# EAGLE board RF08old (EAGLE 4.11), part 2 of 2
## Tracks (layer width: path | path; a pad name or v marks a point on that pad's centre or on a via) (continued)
DMA09  (via drill 0.61) (continued)
  Bottom 0.254: v114.3,77.48 81.92,77.48 v81.28,76.85 | v79.38,72.41 v59.05,72.41 | v59.05,47.01 45.09,47.01 43.81,48.27 RS08.19 40.64,48.27 39.37,49.55 35.56,49.55 v34.29,50.81 | v115.57,81.3 DMA8-11.6 | v149.22,87.01 150.5,87.01 151.13,86.38 IC24.6 | v135.89,101.61 v148.59,101.61 | v138.43,128.28 137.79,128.92 v114.94,128.92
DMA10  (via drill 0.61)
  Top 0.254: v40.64,45.73 41.27,46.37 41.27,50.81 40.01,52.09 41.27,53.36 v41.27,58.44 | v50.8,43.2 v50.8,48.91 | v81.28,57.16 82.55,58.44 v82.55,61.61 | v101.6,62.88 104.14,65.42 104.14,81.3 101.6,83.83 v101.6,91.45
  Bottom 0.254: v41.27,58.44 40.01,59.7 34.92,59.7 33.66,58.44 SV2.21 | v40.64,45.73 RS08.21 43.18,45.1 44.45,43.83 44.45,42.56 45.09,41.92 48.9,41.92 50.16,43.2 v50.8,43.2 | IC24.4 151.13,91.45 149.86,90.19 128.27,90.19 127.64,90.82 123.83,90.82 123.19,91.45 DMA8-11.2 v101.6,91.45 | v50.8,48.91 51.44,49.55 57.15,49.55 59.69,52.09 62.23,52.09 67.31,57.16 v81.28,57.16 | v82.55,61.61 83.82,62.88 v101.6,62.88
DMA11  (via drill 0.61)
  Top 0.254: v31.75,48.27 31.75,53.99 33.02,55.26 SV2.23 | v39.37,48.27 38.73,47.64 38.73,46.37 38.1,45.73 38.1,17.8 v39.37,16.53 | v65.41,19.7 67.31,21.61 67.31,31.77 v69.85,34.3 | v96.52,35.58 103.5,42.56 103.5,63.52 104.78,64.78 104.78,81.93 v104.14,82.56 | v110.49,83.83 114.3,87.64 v114.3,88.28
  Bottom 0.254: RS08.23 27.3,43.2 26.67,42.56 25.4,43.83 25.4,48.27 v31.75,48.27 34.29,45.73 36.83,48.27 v39.37,48.27 | IC24.2 155.57,96.53 156.84,97.81 161.93,97.81 161.93,90.82 161.29,90.19 151.13,90.19 148.59,87.64 124.46,87.64 123.19,88.92 DMA8-11.3 114.94,88.92 v114.3,88.28 | v39.37,16.53 40.01,15.89 61.59,15.89 v65.41,19.7 | v69.85,34.3 76.83,34.3 78.11,35.58 v96.52,35.58 | v104.14,82.56 105.41,83.83 v110.49,83.83
DMA-IN\  (via drill 0.61)
  Top 0.254: v26.67,13.99 22.23,18.43 22.23,33.04 20.32,34.94 20.32,38.12 IC34.1 17.78,48.27 19.68,50.18 19.68,71.77 IC26.1 17.78,76.85 19.05,78.12 19.05,109.23 20.32,110.5 IC13.4
  Bottom 0.254: v26.67,13.99 36.2,13.99 39.37,10.81 71.75,10.81 IC41.12 | IC26.19 21.59,71.14 19.05,73.67 IC26.1
DMA-OUT\  (via drill 0.61)
  Top 0.254: IC28.19 62.87,69.23 62.87,40.02 IC35.19 | v64.77,21.61 v64.77,38.12 | v80.64,18.43 IC41.9 | IC28.1 51.44,71.77 51.44,49.55 52.7,48.27 52.7,41.29 IC35.1
  Bottom 0.254: IC35.1 54.61,40.66 57.15,38.12 IC35.19 v64.77,38.12 | v80.64,18.43 80.01,17.8 68.58,17.8 v64.77,21.61
DONE  (via drill 0.61)
  Top 0.254: v135.25,25.41 135.25,22.24 IC55.2 | v179.07,24.14 181.61,26.69 181.61,61.61 182.25,62.24 182.25,83.2 186.69,87.64 186.69,90.82 184.15,93.36 184.15,113.05 186.69,115.58 | 186.69,115.58 187.96,116.86 IC11.9 | v22.86,36.84 22.86,41.29 22.23,41.92 v22.23,63.52 | v13.97,64.78 14.61,65.42 14.61,90.82 13.97,91.45 13.97,115.58 16.51,118.12 16.51,125.75 20.95,130.19 24.13,130.19 24.13,133.36 21.59,135.9 v21.59,140.35 | v172.09,147.97 186.69,133.36 186.69,115.58
  Bottom 0.254: v135.25,25.41 136.53,26.69 140.34,26.69 142.88,24.14 v179.07,24.14 | v22.86,36.84 33.66,36.84 34.92,38.12 SV1.23 | v22.23,63.52 20.95,64.78 v13.97,64.78 | v21.59,140.35 19.05,142.89 19.05,148.6 55.88,148.6 56.52,149.24 98.42,149.24 99.69,147.97 102.23,147.97 102.87,148.6 120.02,148.6 120.65,147.97 v172.09,147.97
DRV01\  (via drill 0.61)
  Top 0.254: v69.85,12.71 73.66,8.91 IC41.4 | v55.88,12.71 51.44,17.16 v51.44,24.14
  Bottom 0.254: v55.88,12.71 v69.85,12.71 | v51.44,24.14 50.16,25.41 RS08.38
DRV23\  (via drill 0.61)
  Top 0.254: v78.74,44.47 78.11,43.83 78.11,19.7 80.01,17.8 80.01,10.18 81.28,8.91 IC41.7
  Bottom 0.254: v78.74,44.47 47.62,44.47 46.35,45.73 RS08.22
DRVOK\  (via drill 0.61)
  Top 0.254: R2.1 RS08.40 | v46.99,93.36 46.99,97.81 46.35,98.44 46.35,102.25 45.72,102.89 IC21.14 | v53.34,78.75 v53.34,93.36 | v58.42,78.75 57.78,78.12 57.78,43.2 59.05,41.92 59.05,34.94 58.42,34.3 58.42,32.4 57.78,31.77 v57.78,21.61
  Bottom 0.254: IC21.14 46.35,103.52 47.62,103.52 IC21.13 | v53.34,93.36 v46.99,93.36 | v58.42,78.75 v53.34,78.75 | v57.78,21.61 47.62,21.61 46.35,22.88 RS08.40
EIE  (via drill 0.61)
  Top 0.254: IC37.2 194.31,24.14 194.31,8.91 193.68,8.27 187.96,8.27 INTENB.6 | v38.1,3.19 38.1,9.54 35.56,12.08 SV1.3 | v99.69,3.19 102.87,6.36 102.87,19.7 104.14,20.97 v104.14,22.88 | v139.7,24.14 142.88,20.97 142.88,12.08 IC55.9
  Bottom 0.254: IC55.9 146.05,10.18 147.32,8.91 170.18,8.91 171.45,7.63 185.42,7.63 INTENB.6 | v38.1,3.19 v99.69,3.19 | v104.14,22.88 105.41,24.14 v139.7,24.14
ERROR  (via drill 0.61)
  Top 0.254: v147.32,100.34 147.32,36.84 148.59,35.58 148.59,16.53 IC55.10 | v194.31,123.2 194.31,116.22 196.22,114.31 196.22,100.98 IC12.6
  Bottom 0.254: v147.32,100.34 195.58,100.34 196.85,99.08 IC12.6 | v194.31,123.2 191.13,126.38 177.16,126.38 IC7.2
EXAD0\  (via drill 0.61)
  Top 0.254: v4.45,77.48 5.08,76.85 5.08,66.69 7.62,64.15 C35L.34
  Bottom 0.254: v4.45,77.48 19.68,92.72 24.13,92.72 IC20.9
EXAD1\  (via drill 0.61)
  Top 0.254: v8.26,92.72 5.71,90.19 5.71,67.33 6.99,66.06 C35L.36
  Bottom 0.254: v8.26,92.72 8.89,92.72 9.53,93.36 19.68,93.36 IC20.7
EXAD2\  (via drill 0.61)
  Top 0.254: v8.89,94 9.53,93.36 9.53,72.41 8.89,71.77 8.89,70.5 7.62,69.23 C35L.38
  Bottom 0.254: v8.89,94 15.24,94 IC20.5
F.1  (via drill 0.61)
  Top 0.254: SV2.6 35.56,80.03 32.38,80.03 31.75,80.66 31.75,84.47 32.38,85.11 32.38,86.38 31.75,87.01 31.75,101.61 30.48,102.89 IC20.11 30.48,105.42 31.11,106.06 v31.11,111.78 | v194.94,45.73 194.31,46.37 v194.31,81.3 194.31,101.61 v193.68,102.25 | v170.18,111.78 172.09,109.87 v172.09,103.52
  Bottom 0.254: v194.94,45.73 195.58,45.73 IC30.8 | v194.31,81.3 196.85,83.83 FIELD.3 | v31.11,111.78 38.73,111.78 39.37,112.41 39.37,113.68 64.77,113.68 65.41,114.31 88.27,114.31 90.81,111.78 92.08,111.78 92.71,112.41 92.71,113.68 116.84,113.68 120.65,109.87 165.74,109.87 167.64,111.78 v170.18,111.78 | v172.09,103.52 173.35,102.25 v193.68,102.25
F.2  (via drill 0.61)
  Top 0.254: v24.13,83.2 24.13,101.61 25.4,102.89 IC20.13 | v57.78,81.93 57.78,82.56 56.52,83.83 55.24,83.83 55.24,77.48 55.88,76.85 55.88,75.58 55.24,74.95 52.07,74.95 v52.07,78.75 | v85.09,79.39 86.36,78.12 v86.36,76.22 | v113.03,72.41 v111.12,74.31 | v127.64,71.14 127,70.5 v127,63.52 | v196.85,64.78 201.29,69.23 v201.29,78.12
  Bottom 0.254: v24.13,83.2 27.3,80.03 33.66,80.03 34.92,81.3 SV2.4 36.2,81.3 36.83,81.93 55.88,81.93 56.52,81.3 57.15,81.3 v57.78,81.93 | 210.19,77.48 210.19,87.64 200.66,87.64 199.39,86.38 FIELD.2 | 210.19,77.48 210.19,42.56 IC30.11 | v52.07,78.75 53.34,80.03 78.11,80.03 78.74,79.39 80.01,79.39 80.64,78.75 84.45,78.75 v85.09,79.39 | v86.36,76.22 87,75.58 102.23,75.58 103.5,74.31 v111.12,74.31 | v113.03,72.41 124.46,72.41 125.73,71.14 v127.64,71.14 | v127,63.52 168.28,63.52 169.54,64.78 v196.85,64.78 | v201.29,78.12 201.93,77.48 210.19,77.48
F.3  (via drill 0.61)
  Top 0.254: SV2.2 35.56,97.17 v33.66,99.08 v33.66,125.11 | v90.81,121.3 v88.9,123.2 | v158.75,121.94 161.29,121.94 161.29,125.75 v162.56,127.02 | v193.68,127.02 194.31,127.65 194.31,131.46 198.75,135.9 201.29,135.9 201.29,79.39 FIELD.6
  Bottom 0.254: v33.66,99.08 25.4,99.08 IC20.15 | FIELD.6 199.39,76.22 200.66,74.95 207.01,74.95 209.55,72.41 209.55,43.83 206.38,43.83 IC30.13 | v33.66,125.11 34.92,126.38 59.05,126.38 62.87,122.57 88.27,122.57 v88.9,123.2 | v90.81,121.3 91.44,121.94 v158.75,121.94 | v193.68,127.02 v162.56,127.02
GND  (via drill 0.61)
  Top 0.254: IC34.10 17.14,17.16 17.14,16.53 15.88,15.26 10.16,15.26 C35L.1 C35L.3 C35L.5 C35L.7 C35L.9 C35L.11 C35L.13 C35L.15 C35L.17 C35L.19 C35L.21 C35L.23 C35L.25 C35L.27 C35L.29 C35L.31 C35L.33 C35L.35 C35L.37 C35L.39 | C35.2 54.61,43.83 53.98,44.47 53.98,50.18 IC28.10 | SV2.26 v35.56,50.81 | IC21.8 58.42,95.27 54.61,91.45 C28.2 | 92.71,112.41 93.34,111.78 IC16.1 93.98,115.58 96.52,118.12 IC16.15 | 92.71,112.41 92.08,113.05 C16.2 | 92.71,112.41 92.71,99.71 91.44,98.44 C33.2 | IC13.2 IC20.17 | IC14.2 IC14.13 | C42.2 138.43,62.88 137.79,63.52 137.79,73.04 137.16,73.67 DAR8-11.8 135.25,78.12 135.25,84.47 DAR8-11.4 139.06,88.28 139.06,96.53 C27.2 138.43,97.17 140.34,99.08 140.34,111.14 IC17.8 | C24.2 153.03,101.61 149.22,105.42 146.69,105.42 146.69,113.05 C18.2 | IC31.10 153.67,40.66 C38.2 | DAR4-7.4 135.25,50.18 135.25,43.83 DAR4-7.8 137.16,27.32 138.43,26.05 C40.2 | C8.2 123.83,96.53 123.83,88.28 DMA8-11.4 120.02,84.47 120.02,78.12 DMA8-11.8 122.56,75.58 122.56,62.24 C39.2 | DMA0-3.4 120.02,19.7 120.02,26.05 121.92,27.96 C46.2 | D36L.1 D36L.3 D36L.5 D36L.7 D36L.9 D36L.11 D36L.13 D36L.15 D36L.17 D36L.19 D36L.21 D36L.23 D36L.25 D36L.27 D36L.29 D36L.31 D36L.33 D36L.35 D36L.37 D36L.39 | D35L.1 D35L.3 D35L.5 D35L.7 D35L.9 D35L.11 D35L.13 D35L.15 D35L.17 D35L.19 D35L.21 D35L.23 D35L.25 D35L.27 D35L.29 D35L.31 D35L.33 D35L.35 D35L.37 D35L.39 | RS08.39 43.18,23.51 44.45,24.78 44.45,31.13 43.18,32.4 RS08.31 | 62.87,26.05 62.87,24.78 IC35.13 62.87,20.97 62.87,16.53 59.05,12.71 | IC35.15 62.87,26.05 | 62.87,26.05 62.87,31.13 IC35.17 | 59.05,12.71 54.61,17.16 54.61,17.8 IC35.10
  Top 0.254: 59.05,12.71 62.87,8.91 C41.2 | J14.2 J13.2 J12.2 J11.2 J10.2 J9.2 J8.2 | IC24.10 153.67,74.95 C31.2 | D34L.39 D34L.37 D34L.35 D34L.33 D34L.31 D34L.29 D34L.27 D34L.25 D34L.23 D34L.21 D34L.19 D34L.17 D34L.15 D34L.13 D34L.11 D34L.9 D34L.7 D34L.5 D34L.3 D34L.1 172.72,22.24 173.99,20.97 173.99,13.35 172.72,12.08 C43.2 | 161.93,14.62 161.93,15.89 | 161.93,15.89 IC38.15 | IC38.13 161.93,14.62 | 161.93,15.89 161.93,20.97 IC38.17 | 161.93,14.62 161.93,9.54 IC38.11 | v185.42,99.08 186.69,97.81 186.69,92.09 187.96,90.82 IC19.7 | C36L.39 C36L.37 C36L.35 C36L.33 C36L.31 C36L.29 C36L.27 C36L.25 C36L.23 C36L.21 C36L.19 C36L.17 C36L.15 C36L.13 C36L.11 C36L.9 C36L.7 C36L.5 C36L.3 C36L.1 190.5,21.61 193.04,19.07 INTENB.9 189.23,13.99 | 189.23,13.99 INTENB.5 | 189.23,13.99 INTENB.8 | C37.2 199.39,33.67 197.49,35.58 197.49,37.48 IC30.10 | FIELD.8 196.22,73.04 196.22,76.85 FIELD.5 197.49,79.39 197.49,80.66 FIELD.4 200.03,83.2 200.03,91.45 C44.2 199.39,95.27 IC12.7 200.03,98.44 200.03,114.31 C12.2 199.39,114.95 200.66,116.22 200.66,129.55 IC8.1 199.39,133.36 C47.2 | IC7.8 190.5,123.2 191.77,121.94 191.77,114.31 190.5,113.05 IC11.7 | 173.35,135.27 175.26,133.36 IC7.15 | 173.35,135.27 173.35,138.44 C45.- | C11.2 172.72,113.68 170.18,116.22 C7.2 170.18,126.38 171.45,127.65 171.45,133.36 173.35,135.27 | IC9.12 124.46,130.82 123.19,129.55 123.19,127.02 121.92,125.75 IC9.2 | C17.2 119.38,113.68 116.84,116.22 C9.2 116.84,126.38 118.11,127.65 118.11,136.54 116.84,137.81 C5.2 | IC10.12 152.4,130.82 151.13,129.55 151.13,127.65 149.86,126.38 IC10.2 | C6.2 144.78,137.81 144.15,137.17 144.15,132.09 143.51,131.46 143.51,127.65 144.78,126.38 C10.2
  Top 0.254: IC4.7 107.31,136.54 108.58,136.54 IC4.8 | IC3.7 79.38,136.54 80.64,136.54 IC3.8 | IC2.7 51.44,136.54 52.7,136.54 IC2.8 | IC17.15 127.64,122.57 130.81,122.57 130.81,125.75 131.44,126.38 134.62,126.38 IC9.7
  Bottom 0.254: C35L.17 C34.2 | SV2.26 SV2.25 32.38,53.36 31.75,52.72 27.3,52.72 26.67,52.09 20.32,52.09 19.05,50.81 IC26.10 C35L.23 | J2.2 5.71,50.81 6.99,52.09 8.26,52.09 9.53,53.36 C35L.25 | v35.56,50.81 36.2,50.18 40.01,50.18 40.64,49.55 46.35,49.55 46.99,50.18 51.44,50.18 52.07,50.81 IC28.10 | C22.2 59.69,97.81 IC21.8 56.52,98.44 38.1,98.44 C21.2 30.48,97.81 IC20.10 | IC25.8 99.69,71.77 95.89,71.77 IC25.5 92.08,71.77 83.19,71.77 80.01,74.95 | 80.01,74.95 56.52,74.95 55.24,76.22 C28.2 | 80.01,74.95 C25.2 | IC22.7 85.09,97.81 C33.2 | IC16.8 109.86,109.87 95.89,109.87 IC16.1 93.34,111.14 84.45,111.14 IC15.7 81.92,113.68 74.3,113.68 | IC17.15 121.92,116.86 99.06,116.86 IC16.15 | IC20.10 30.48,95.27 26.04,90.82 24.77,90.82 19.68,85.74 19.05,85.74 C26.2 2.54,76.22 2.54,74.95 3.81,73.67 6.99,73.67 9.53,71.14 C35L.39 | C13.2 10.79,113.05 11.43,112.41 12.06,112.41 IC13.1 13.34,111.14 14.61,111.14 IC13.2 17.14,109.87 26.04,109.87 IC13.7 | 6.35,98.44 10.16,102.25 13.34,102.25 IC20.17 | 6.35,98.44 5.71,97.81 C20.2 | 74.3,113.68 66.04,113.68 C15.2 57.15,113.05 IC14.7 53.98,109.87 46.35,109.87 | 74.3,113.68 IC15.4 | IC13.7 29.21,113.05 C14.2 | 46.35,109.87 45.09,109.87 IC14.2 42.55,111.14 41.27,111.14 IC14.1 40.64,110.5 29.21,110.5 IC13.7 | 46.35,109.87 IC14.4 | 6.35,98.44 28.57,98.44 IC20.10 | IC17.8 140.34,112.41 146.05,112.41 146.69,113.05 C18.2 147.96,113.05 148.59,113.68 172.72,113.68 | IC31.10 151.13,41.92 149.86,40.66 139.7,40.66 138.43,41.92 DAR4-7.8 135.89,41.92 134.62,40.66 125.09,40.66 123.83,41.92 DMA4-7.8 120.65,41.92 119.38,43.2 D36L.17 | D36L.5 C46.2 | DMA4-7.4 120.65,52.09 119.38,53.36 D36L.25
  Bottom 0.254: C39.2 122.56,62.24 121.28,63.52 D36L.33 | C27.2 137.79,96.53 136.53,97.81 126.36,97.81 125.09,96.53 C8.2 | 80.01,23.51 79.38,22.88 D35L.1 | 80.01,23.51 80.64,24.14 C36.2 | 80.01,23.51 82.55,20.97 89.53,20.97 IC36.4 92.08,22.24 93.34,22.24 IC36.5 95.89,20.97 99.69,20.97 IC36.8 102.23,22.24 102.87,22.24 103.5,21.61 112.39,21.61 113.67,22.88 D36L.1 | D35L.31 79.38,60.98 80.64,59.7 C29.2 81.28,60.34 92.08,60.34 IC29.5 95.89,56.53 99.69,56.53 IC29.8 | D35L.19 79.38,45.73 80.64,44.47 C32.2 81.28,45.1 92.08,45.1 | 92.08,45.1 IC32.5 | 92.08,45.1 99.69,45.1 IC32.8 | DMA0-3.8 IC23.7 107.31,5.73 98.42,5.73 IC23.2 94.61,9.54 91.44,9.54 C23.2 85.09,8.91 IC41.8 81.92,9.54 63.5,9.54 C41.2 | RS08.31 43.81,33.04 45.09,34.3 54.61,34.3 55.88,33.04 IC35.17 | D35L.5 73.03,27.96 71.75,26.69 66.67,26.69 65.41,27.96 IC35.15 | D34L.17 J6.2 | C31.2 154.31,67.33 155.57,68.59 168.28,68.59 169.54,67.33 170.81,67.33 172.09,68.59 D34L.37 | D34L.13 J8.2 | IC55.7 138.43,7.63 139.7,6.36 149.86,6.36 151.13,7.63 IC38.10 IC38.11 | IC38.13 161.29,12.71 161.93,12.08 172.72,12.08 C43.2 173.35,11.45 173.99,12.08 180.97,12.08 INTENB.4 183.51,9.54 184.78,9.54 INTENB.5 | IC19.7 190.5,91.45 C44.2 | v185.42,99.08 C19.2 | C36L.21 IC30.6 | FIELD.9 FIELD.8 C36L.39 | C36L.33 C30.2 | INTENB.8 195.58,7.63 IC37.10 | INTENB.9 IC37.6 | C36L.13 IC30.10 | C12.2 198.75,114.31 197.49,113.05 191.77,113.05 IC11.7 188.59,113.68 172.72,113.68 | IC6.8 167,139.08 171.45,139.08 C45.- | IC18.7 166.37,113.05 C11.2 172.72,113.68 | IC7.1 171.45,125.75 C7.2 163.83,125.75 IC10.7 160.66,126.38 147.96,126.38 | IC17.1 120.65,113.05 C17.2
  Bottom 0.254: C9.2 116.84,126.38 120.02,126.38 IC9.2 123.83,126.38 132.72,126.38 IC9.7 135.89,125.75 C10.2 144.78,126.38 147.96,126.38 | IC5.7 135.25,137.81 144.78,137.81 C6.2 | 147.96,126.38 IC10.2 | C5.2 116.2,138.44 115.57,137.81 109.86,137.81 IC4.8 | IC3.8 81.92,137.81 87.63,137.81 88.27,138.44 C4.2 88.9,139.08 104.78,139.08 IC4.7 | IC2.8 53.98,137.81 59.69,137.81 60.33,138.44 C3.2 60.96,139.08 76.83,139.08 IC3.7 | C1.2 5.71,138.44 6.35,139.08 20.95,139.08 IC1.7 23.5,136.54 24.77,136.54 IC1.8 26.04,137.81 31.75,137.81 32.38,138.44 C2.2 33.02,139.08 48.9,139.08 IC2.7
INT_RQ\  (via drill 0.61)
  Top 0.254: IC55.3 135.25,15.89 135.25,12.08 IC55.6 | v149.22,55.9 149.22,12.08 IC55.8
  Bottom 0.254: IC55.6 138.43,10.18 140.97,7.63 IC55.8 | v149.22,55.9 153.67,55.9 156.21,58.44 D34L.30
IOS\  (via drill 0.61)
  Top 0.254: v111.76,131.46 111.76,128.92 90.81,128.92 82.55,120.67 82.55,109.23 78.74,105.42 IC22.10 | v186.69,135.9 189.23,133.36 v189.23,99.08 | v169.54,92.09 168.91,91.45 168.91,57.8 170.18,56.53 D34L.28
  Bottom 0.254: v111.76,131.46 114.94,134.63 157.48,134.63 158.12,135.27 186.06,135.27 v186.69,135.9 | v189.23,99.08 189.23,92.09 v169.54,92.09
MYDEV\
  Top 0.254: 90.17,55.9 91.44,57.16 IC29.4 | 90.17,55.9 90.17,45.73 91.44,44.47 IC32.4 | 90.17,55.9 90.17,71.14 91.44,72.41 IC25.4
  Bottom 0.254: IC32.4 99.06,35.58 PAD1.1
N$1
  Top 0.254: IC36.9 PAD8.1
N$2  (via drill 0.61)
  Top 0.254: v179.07,129.55 181.61,127.02 181.61,121.94 182.88,120.67 IC11.11
  Bottom 0.254: v179.07,129.55 165.1,129.55 IC10.8
N$3  (via drill 0.61)
  Top 0.254: v125.73,49.55 126.36,48.91 126.36,40.66 125.09,39.38 125.09,31.77 125.73,31.13 125.73,30.5 125.09,29.86 125.09,18.43 DMA0-3.5
  Bottom 0.254: v125.73,49.55 DMA4-7.12
N$4  (via drill 0.61)
  Top 0.254: SW1.1 8.26,123.84 9.53,123.84 SW1.2 10.79,123.84 12.06,123.84 SW1.3 13.34,123.84 14.61,123.84 SW1.4 | 19.05,123.84 18.41,123.84 SW1.5 | 19.05,123.84 19.68,123.84 SW1.6 20.95,123.84 22.23,123.84 SW1.7 | v49.53,115.58 49.53,110.5 46.99,107.97 46.99,99.08 48.26,97.81 IC21.4 | v20.32,114.31 19.05,115.58 19.05,123.84
  Bottom 0.254: SW1.5 17.14,123.84 15.88,123.84 SW1.4 | SW1.8 24.77,123.84 23.5,123.84 SW1.7 | v49.53,115.58 26.67,115.58 25.4,114.31 v20.32,114.31
N$5
  Top 0.254: IC36.15 PAD2.1
N$6
  Top 0.254: IC36.14 PAD3.1
N$7
  Top 0.254: IC36.13 PAD4.1
N$8
  Top 0.254: IC36.12 PAD5.1
N$9
  Top 0.254: IC36.11 PAD6.1
N$10
  Top 0.254: IC36.10 PAD7.1
N$11  (via drill 0.61)
  Top 0.254: v104.14,27.96 PAD9.1
  Bottom 0.254: IC36.7 v104.14,27.96
N$12  (via drill 0.61)
  Top 0.254: DAR4-7.14 142.88,56.53 142.88,60.34 143.51,60.98 144.78,60.98 144.78,73.67 142.88,75.58 142.88,87.01 DAR8-11.14 146.69,90.82 146.69,98.44 146.05,99.08 v146.05,116.86
  Bottom 0.254: v146.05,116.86 162.56,116.86 IC18.8
N$13  (via drill 0.61)
  Top 0.254: v132.72,50.81 132.08,51.45 132.08,81.3 DMA8-11.12
  Bottom 0.254: v132.72,50.81 124.46,50.81 123.19,49.55 DMA4-7.5
N$14  (via drill 0.61)
  Top 0.254: v31.11,114.31 31.11,114.95 27.94,118.12 IC13.8 | v81.28,115.58 IC15.6
  Bottom 0.254: v31.11,114.31 50.8,114.31 | 50.8,114.31 IC14.8 | v81.28,115.58 80.64,114.95 53.98,114.95 53.34,114.31 50.8,114.31
N$15  (via drill 0.61)
  Top 0.254: v41.91,149.88 41.91,142.25 45.72,138.44 IC2.5 | v120.65,149.24 120.65,140.35 121.92,139.08 IC5.2
  Bottom 0.254: v41.91,149.88 99.06,149.88 100.33,148.6 101.6,148.6 102.23,149.24 v120.65,149.24
N$16  (via drill 0.61)
  Top 0.254: v133.99,71.14 133.99,50.81 133.35,50.18 133.35,8.91 128.27,8.91 126.36,10.81 126.36,15.26 DMA0-3.12 | v125.09,73.04 125.09,83.2 v124.46,83.83
  Bottom 0.254: v133.99,71.14 132.08,73.04 v125.09,73.04 | v124.46,83.83 125.73,85.11 132.72,85.11 133.99,83.83 DAR8-11.5
N$17
  Top 0.254: SW2.1 36.2,123.84 37.47,123.84 SW2.2 38.73,123.84 40.01,123.84 SW2.3 41.27,123.84 42.55,123.84 SW2.4 43.81,123.84 45.09,123.84 SW2.5 46.35,123.84 47.62,123.84 SW2.6 | IC21.5 50.8,97.81 52.07,99.08 52.07,121.94 50.8,123.2 SW2.7 51.44,123.84 52.7,123.84 SW2.8
  Bottom 0.254: SW2.6 48.9,123.84 50.16,123.84 SW2.7
N$19
  Top 0.254: IC21.6 53.34,97.81 54.61,99.08 54.61,120.67 57.78,123.84 62.87,123.84 SW3.1 | SW3.2 66.67,123.84 67.94,123.84 SW3.3 69.22,123.84 70.48,123.84 SW3.4 71.75,123.84 73.03,123.84 SW3.5 74.3,123.84 75.56,123.84 SW3.6 | SW3.8 80.64,123.84 79.38,123.84 SW3.7
  Bottom 0.254: SW3.2 65.41,123.84 64.14,123.84 SW3.1 | SW3.7 78.11,123.84 76.83,123.84 SW3.6
N$20  (via drill 0.61)
  Top 0.254: v57.15,117.49 57.15,99.08 55.88,97.81 IC21.7 | SW4.1 92.08,123.84 93.34,123.84 SW4.2 94.61,123.84 95.89,123.84 SW4.3 97.16,123.84 98.42,123.84 SW4.4 99.69,123.84 100.97,123.84 SW4.5 102.23,123.84 103.5,123.84 SW4.6 104.78,123.84 106.05,123.84 SW4.7 107.31,123.84 108.58,123.84 SW4.8
  Bottom 0.254: v57.15,117.49 61.59,121.94 88.9,121.94 SW4.1
N$21  (via drill 0.61)
  Top 0.254: v100.33,149.88 73.66,149.88 69.85,146.06 69.85,142.25 73.66,138.44 IC3.5 | v122.56,149.24 125.73,146.06 125.73,139.71 127,138.44 IC5.4
  Bottom 0.254: v100.33,149.88 100.97,150.51 121.28,150.51 v122.56,149.24
N$22  (via drill 0.61)
  Top 0.254: 127.64,52.72 127.64,41.29 129.54,39.38 129.54,26.69 128.27,26.69 127.64,26.05 127.64,22.24 DMA0-3.14 | 127.64,52.72 DMA4-7.14 | 127.64,52.72 127.64,60.98 128.91,60.98 129.54,61.61 129.54,73.04 127.64,74.95 127.64,87.01 DMA8-11.14 127,91.45 127,99.08 v133.99,106.06 | v158.12,106.7 158.12,107.33 IC18.6
  Bottom 0.254: v158.12,106.7 157.48,106.06 v133.99,106.06
N$23
  Bottom 0.254: IC1.5 19.68,135.27 79.38,135.27 80.01,135.9 80.01,139.71 118.11,139.71 119.38,138.44 IC5.1
N$24
  Bottom 0.254: IC4.5 103.5,135.27 127.64,135.27 IC5.5
N$25  (via drill 0.61)
  Top 0.254: v141.6,58.44 141.6,47.01 139.7,47.01 DAR4-7.5 | v148.59,58.44 147.96,59.07 147.96,81.93 v148.59,82.56
  Bottom 0.254: v141.6,58.44 v148.59,58.44 | v148.59,82.56 147.32,83.83 DAR8-11.12
N$26  (via drill 0.61)
  Top 0.254: v103.5,100.98 105.41,102.89 105.41,116.86 106.68,118.12 IC16.11 | IC22.1 v68.58,99.71
  Bottom 0.254: v68.58,99.71 69.85,100.98 v103.5,100.98
N$27  (via drill 0.61)
  Top 0.254: v127.64,106.06 129.54,107.97 IC17.4
  Bottom 0.254: v127.64,106.06 125.09,106.06 124.46,106.7 123.83,106.06 93.34,106.06 92.71,105.42 88.9,105.42 88.27,106.06 78.11,106.06 IC22.11
N$28
  Top 0.254: IC19.1 172.72,90.19 168.91,94 168.91,139.08 172.09,142.25 176.53,142.25 176.53,138.44 181.61,133.36 181.61,128.28 182.88,127.02 IC7.5
N$29
  Top 0.254: RA.2 RB.1 208.28,122.57 209.55,123.84 209.55,125.75 IC8.7
N$30
  Top 0.254: IC12.2 197.49,109.87 197.49,111.14 IC12.1 198.12,117.49 200.03,119.39 200.03,125.11 IC8.3
  Bottom 0.254: IC8.3 196.22,128.92 195.58,128.92 RL.2
N$31
  Top 0.254: IC18.11 157.48,120.67 156.21,121.94 156.21,129.55 157.48,130.82 IC10.10
N$32
  Top 0.254: RB.2 197.49,121.94 196.22,123.2 196.22,127.65 IC8.2
  Bottom 0.254: 200.03,129.55 201.93,129.55 204.47,127.02 IC8.6 | IC8.2 200.03,129.55 | 200.03,129.55 204.47,134 C47.1
N$33
  Top 0.254: IC19.11 180.34,97.81 181.61,99.08 181.61,115.58 184.15,118.12 184.15,129.55 182.88,130.82 IC7.12
N$34
  Top 0.254: IC8.5 C48.2
N$37
  Top 0.254: IC12.9 205.1,99.71 205.1,100.98 IC12.10 205.1,102.25 205.1,103.52 IC12.11
N$40
  Bottom 0.254: IC12.5 199.39,101.61 204.47,96.53 IC12.8
N$53
  Bottom 0.254: SW1.16 9.53,130.19 13.34,130.19 13.97,130.82 13.97,136.54 14.61,136.54 IC1.4
N$54
  Top 0.254: SW1.15 10.16,133.36 12.7,135.9 IC1.3
N$55
  Bottom 0.254: SW1.14 12.7,133.36 10.16,135.9 IC1.2
N$56
  Top 0.254: IC1.1 7.62,135.9 8.89,134.63 8.89,130.82 9.53,130.19 14.61,130.19 14.61,131.46 SW1.13
N$57
  Top 0.254: SW1.11 17.78,129.55 6.35,129.55 6.35,138.44 IC1.14
N$58
  Top 0.254: SW1.10 19.05,135.9 19.05,139.71 15.24,143.52 IC1.13
N$59
  Top 0.254: SW1.9 25.4,133.36 24.13,134.63 24.13,139.08 20.32,142.89 17.78,142.89 IC1.12
N$60
  Top 0.254: SW1.12 13.97,135.9 13.97,146.06 13.34,146.7 10.16,146.7 IC1.15
N$61
  Top 0.254: SW2.16 35.56,133.36 36.83,134.63 36.83,138.44 37.47,139.08 42.55,139.08 42.55,137.81 IC2.4
N$62
  Top 0.254: SW2.15 38.1,133.36 40.64,135.9 IC2.3
N$63
  Top 0.254: SW2.14 38.73,130.19 36.83,130.19 36.83,133.36 38.1,134.63 IC2.2
N$64
  Top 0.254: IC2.1 35.56,135.9 34.29,134.63 34.29,130.82 35.56,129.55 42.55,129.55 42.55,131.46 SW2.13
N$65
  Top 0.254: SW2.11 44.45,135.9 44.45,138.44 40.64,142.25 IC2.14
N$66
  Top 0.254: SW2.10 46.99,135.9 46.99,139.71 43.18,143.52 IC2.13
N$67
  Top 0.254: SW2.9 49.53,135.9 49.53,139.71 45.72,143.52 IC2.12
N$68
  Top 0.254: SW3.16 63.5,133.36 64.14,134 64.14,135.27 64.77,135.9 64.77,138.44 65.41,139.08 70.48,139.08 70.48,137.81 IC3.4
N$69
  Top 0.254: SW3.15 66.04,133.36 68.58,135.9 IC3.3
N$70
  Top 0.254: SW3.14 66.67,130.19 64.77,130.19 64.77,134.63 66.04,135.9 IC3.2
N$71
  Top 0.254: IC3.1 63.5,135.9 62.23,134.63 62.23,130.82 63.5,129.55 70.48,129.55 70.48,131.46 SW3.13
N$72
  Top 0.254: SW3.11 72.39,135.9 72.39,138.44 68.58,142.25 IC3.14
N$73
  Top 0.254: SW3.10 74.93,135.9 74.93,139.71 71.12,143.52 IC3.13
N$74
  Top 0.254: SW3.9 77.47,135.9 77.47,139.71 73.66,143.52 IC3.12
N$75
  Top 0.254: SW4.16 93.34,130.19 97.79,130.19 97.79,134.63 99.06,135.9 IC4.4
N$76
  Top 0.254: SW4.15 93.98,133.36 96.52,135.9 IC4.3
N$77
  Bottom 0.254: SW4.14 96.52,133.36 93.98,135.9 IC4.2
N$78
  Bottom 0.254: SW4.13 97.16,130.19 93.34,130.19 92.71,130.82 92.71,135.9 91.44,135.9 IC4.1
N$79
  Top 0.254: SW4.11 104.14,133.36 102.87,134.63 102.87,140.98 100.33,143.52 100.33,146.06 99.69,146.7 96.52,146.7 IC4.14
N$80
  Top 0.254: SW4.10 104.78,130.19 102.87,130.19 102.87,133.36 100.33,135.9 100.33,142.25 99.06,143.52 IC4.13
N$81
  Top 0.254: SW4.9 105.41,135.9 105.41,139.71 101.6,143.52 IC4.12
N$82
  Top 0.254: SW4.12 99.06,129.55 89.53,129.55 89.53,137.17 90.17,137.81 90.17,138.44 93.98,142.25 IC4.15
N$83
  Top 0.254: SW3.12 73.66,130.82 70.48,127.65 62.23,127.65 62.23,129.55 61.59,130.19 61.59,137.17 62.23,137.81 62.23,139.71 66.04,143.52 IC3.15
N$84
  Top 0.254: SW2.12 45.72,130.82 42.55,127.65 33.66,127.65 33.66,137.17 34.29,137.81 34.29,139.71 38.1,143.52 IC2.15
NXD  (via drill 0.61)
  Top 0.254: v101.6,3.83 104.14,6.36 IC23.5 | v36.83,5.73 34.29,8.27 34.29,18.43 33.66,19.07 31.75,19.07 31.75,26.05 32.38,26.69 34.29,26.69 34.29,28.59 35.56,29.86 SV1.17 | v189.23,39.38 189.23,16.53 184.15,11.45 v184.15,2.56
  Bottom 0.254: v36.83,5.73 38.73,3.83 83.82,3.83 84.45,4.46 100.97,4.46 v101.6,3.83 104.14,1.28 182.88,1.28 v184.15,2.56 | v189.23,39.38 199.39,39.38 204.47,44.47 207.65,44.47 207.65,51.45 207.01,52.09 204.47,52.09 203.84,52.72 200.03,52.72 199.39,53.36 IC30.4
NXD\  (via drill 0.61)
  Top 0.254: v176.53,4.46 176.53,1.92 112.39,1.92 IC23.6 | v208.91,8.91 210.19,10.18 210.19,108.6 208.91,109.87 207.65,109.87 207.65,108.6 IC12.12
  Bottom 0.254: v176.53,4.46 177.8,5.73 201.29,5.73 204.47,8.91 v208.91,8.91
PBIT  (via drill 0.61)
  Top 0.254: v87.63,120.67 90.17,120.67 90.81,120.03 92.71,120.03 92.71,120.67 93.34,121.3 97.79,121.3 97.79,115.58 95.25,113.05 95.25,100.34 92.71,97.81 v92.71,56.53 | v66.04,49.55 64.77,48.27 v64.77,41.92 | v57.78,40.02 57.78,33.04 57.15,32.4 57.15,22.24 56.52,21.61 56.52,20.97 59.69,17.8 IC35.11 | v53.34,115.58 IC14.6
  Bottom 0.254: v53.34,115.58 53.98,116.22 62.23,116.22 67.31,121.3 87,121.3 v87.63,120.67 | v92.71,56.53 88.9,52.72 77.47,52.72 74.3,49.55 v66.04,49.55 | v64.77,41.92 59.69,41.92 v57.78,40.02
PCA  (via drill 0.61)
  Top 0.254: v191.13,104.79 191.13,72.41 193.68,69.86 193.68,32.4 196.85,29.23 200.03,29.23 200.03,22.24 199.39,21.61 196.22,21.61 196.22,14.62 IC37.8
  Bottom 0.254: IC55.5 138.43,12.71 139.7,13.99 195.58,13.99 196.85,12.71 IC37.8 | v191.13,104.79 194.94,104.79 196.85,106.7 IC12.3
PER  (via drill 0.61)
  Top 0.254: v133.35,142.89 133.35,142.25 130.81,139.71 130.81,134.63 132.08,133.36 IC9.9 | v196.22,142.25 201.93,136.54 201.93,78.75 202.56,78.12 202.56,62.88 200.66,60.98 | IC30.2 200.66,60.98 | v27.3,34.3 27.94,33.67 27.94,12.08 38.1,1.92 87,1.92 87,19.07 v86.36,19.7 | v200.03,19.07 200.66,19.7 200.66,60.98
  Bottom 0.254: v133.35,142.89 143.51,142.89 144.15,142.25 v196.22,142.25 | v27.3,34.3 33.66,34.3 34.92,35.58 SV1.21 | v86.36,19.7 107.31,19.7 107.95,20.34 119.38,20.34 120.65,19.07 173.99,19.07 174.62,19.7 196.22,19.7 196.85,19.07 v200.03,19.07
PER\  (via drill 0.61)
  Top 0.254: v142.88,132.09 142.88,121.3 144.15,120.03 v144.15,104.16
  Bottom 0.254: v144.15,104.16 144.78,104.79 181.61,104.79 182.88,103.52 197.49,103.52 IC12.4 | v142.88,132.09 IC9.8
PIE  (via drill 0.61)
  Top 0.254: v173.35,3.83 177.16,7.63 177.16,8.27 177.8,8.91 INTENB.2 | v145.41,3.83 140.34,8.91 v140.34,15.26 | v206.38,32.4 206.38,33.04 203.84,35.58 203.84,51.45 IC30.17
  Bottom 0.254: SV1.5 62.23,15.26 64.14,17.16 80.64,17.16 81.28,17.8 114.3,17.8 115.57,16.53 134.62,16.53 135.89,15.26 IC55.4 v140.34,15.26 | v145.41,3.83 v173.35,3.83 173.99,3.19 176.53,3.19 177.8,4.46 205.1,4.46 207.65,7 210.19,7 210.19,28.59 v206.38,32.4
PROTECT
  Bottom 0.254: IC5.6 133.99,135.27 150.5,135.27 IC6.3
SETNXD\  (via drill 0.61)
  Top 0.254: v62.87,95.9 v62.87,102.89 | v95.25,94.63 95.25,29.23 100.33,24.14 100.33,10.18 101.6,8.91 IC23.4
  Bottom 0.254: v62.87,102.89 59.69,102.89 IC21.9 | v62.87,95.9 64.14,94.63 71.75,94.63 72.39,94 84.45,94 85.09,94.63 v95.25,94.63
SETPER\  (via drill 0.61)
  Top 0.254: v24.13,128.92 24.13,114.31 22.86,113.05 IC13.5 | v114.3,127.65 113.67,128.28 113.67,138.44 118.11,142.89 118.11,147.97 120.65,150.51 128.27,150.51 128.27,134.63 129.54,133.36 IC9.10
  Bottom 0.254: v24.13,128.92 24.77,128.28 113.67,128.28 v114.3,127.65
SETWLS\  (via drill 0.61)
  Top 0.254: v161.29,127.02 161.29,134.63 162.56,135.9 IC6.7 | v130.18,127.65 IC9.4
  Bottom 0.254: v130.18,127.65 130.81,127.02 v161.29,127.02
SKIP\  (via drill 0.61)
  Top 0.254: IC19.6 185.42,90.19 182.88,92.72 IC19.10 v182.88,105.42 | v124.46,105.42 IC17.2
  Bottom 0.254: R1.1 170.81,86.38 171.45,87.01 173.35,87.01 IC19.2 177.16,87.01 183.51,87.01 IC19.6 | v124.46,105.42 125.09,104.79 142.24,104.79 142.88,105.42 v182.88,105.42
START\  (via drill 0.61)
  Top 0.254: 131.44,45.1 131.44,14.62 DMA0-3.11 | 131.44,45.1 DMA4-7.11 | 131.44,45.1 131.44,79.39 DMA8-11.11 | v154.31,107.97 154.31,109.87 154.94,110.5 IC18.3 | v139.06,107.97 137.16,106.06 137.16,96.53 133.99,93.36 133.99,81.93 v133.35,81.3
  Bottom 0.254: v154.31,107.97 153.67,107.33 149.86,107.33 148.59,108.6 139.7,108.6 v139.06,107.97 | v133.35,81.3 DMA8-11.11
VCC  (via drill 0.61)
  Top 0.508: C14.1 38.73,118.12 40.01,119.39 IC14.14 40.64,118.12 41.91,116.86 41.91,106.7 | 41.91,106.7 40.64,105.42 IC21.16 | 41.91,106.7 45.72,110.5 IC14.3 | C13.1 10.16,117.49 7.62,114.95 IC20.20 | IC1.16 7.62,146.06 10.16,148.6 33.02,148.6 C2.1 | C20.1 5.08,103.52 3.81,104.79 3.81,141.62 5.08,142.89 C1.1 | IC36.6 96.52,21.61 93.98,19.07 IC23.14 | C29.1 81.28,64.15 80.01,62.88 80.01,51.45 81.28,50.18 C32.1 81.28,48.91 82.55,47.64 82.55,33.04 83.82,31.77 IC36.16 v83.82,26.69 | IC25.16 83.82,76.22 85.09,74.95 85.09,72.41 83.82,71.14 IC29.16 | 90.17,116.22 90.17,104.79 91.44,103.52 C33.1 | 90.17,116.22 91.44,117.49 C16.1 | 73.03,113.68 73.66,113.05 IC15.3 | v73.03,116.22 73.03,113.68 | 64.77,123.2 64.77,126.38 62.23,126.38 59.69,128.92 59.69,141.62 60.96,142.89 C3.1 | 64.77,123.2 66.04,121.94 76.83,121.94 76.83,121.3 77.47,120.67 77.47,118.12 73.03,113.68 | 90.17,116.22 87.63,116.22 v87.63,116.86 | IC35.20 59.69,41.92 C35.1 | v46.35,13.99 46.35,8.91 45.72,8.27 R2.2 | C41.1 v63.5,39.38 63.5,60.98 | IC34.20 24.13,41.92 C34.1 | IC26.20 24.13,74.95 C26.1 | v20.32,73.67 v20.32,44.47 | 63.5,60.98 63.5,71.14 IC28.20 59.69,74.95 C28.1 60.33,76.22 v60.33,107.97 60.33,121.94 63.5,121.94 64.77,123.2 | 63.5,60.98 v64.14,60.98 | IC38.20 158.75,31.77 C38.1 | IC55.14 143.51,24.14 C40.1 | v166.37,30.5 166.37,13.99 169.54,13.99 172.09,16.53 C43.1 | C44.1 204.47,90.19 FIELD.16 203.84,87.01 203.84,63.52 C30.1 204.47,62.24 IC30.20 203.2,58.44 203.2,34.94 204.47,33.67 C37.1 204.47,31.77 IC37.20 | J7.2 177.8,41.29 175.9,43.2 175.9,43.83 177.8,45.73 J5.2 J4.2 J3.2 v177.8,60.98 | C31.1 158.75,66.06 IC31.20 158.75,64.78 v154.94,60.98
  Top 0.508: 127,60.34 v126.36,59.7 | 127,60.34 127,61.61 127.64,62.24 C39.1 | 127,60.34 127,40.66 127.64,40.02 127.64,29.23 128.27,28.59 C46.1 | IC18.14 149.86,120.67 148.59,121.94 148.59,129.55 147.32,130.82 IC10.14 | IC6.16 147.32,143.52 146.69,142.89 146.69,139.08 146.05,138.44 146.05,134.63 144.78,133.36 C10.1 | IC17.16 121.92,120.67 120.65,121.94 120.65,129.55 119.38,130.82 IC9.14 119.38,133.36 120.65,134.63 120.65,139.08 119.38,140.35 IC5.14 | v91.44,140.98 IC4.16 | DMA8-11.16 128.27,95.27 C8.1 | C27.1 143.51,95.27 DAR8-11.16 142.24,91.45 142.24,64.15 143.51,62.88 C42.1 | IC24.20 158.75,100.34 C24.1 | R1.2 IC19.14 C19.1 172.72,99.71 173.35,100.34 173.35,111.78 173.99,112.41 173.99,114.95 172.72,116.22 C11.1 | C48.1 208.28,130.19 207.01,131.46 207.01,132.09 IC8.8 203.84,130.19 203.84,118.12 204.47,117.49 C12.1 204.47,113.05 IC12.14 | RL.1 RA.1 198.12,120.03 199.39,121.3 199.39,123.2 IC8.4 | IC11.4 182.88,113.05 185.42,115.58 IC11.10 | IC7.16 172.72,130.82 173.99,129.55 173.99,121.94 175.26,120.67 IC11.14 | v118.75,115.58 119.38,116.22 C17.1
  Bottom 0.508: IC21.16 40.01,103.52 39.37,103.52 38.73,102.89 C21.1 38.1,102.25 44.45,102.25 | 44.45,102.25 52.07,102.25 52.07,105.42 52.7,106.06 62.23,106.06 65.41,102.89 C22.1 66.67,102.89 67.31,103.52 67.94,103.52 IC22.14 68.58,105.42 66.04,107.97 v60.33,107.97 | C13.1 10.79,118.12 11.43,118.76 12.06,118.76 IC13.14 | C20.1 5.71,102.89 6.35,103.52 6.99,103.52 IC20.20 7.62,106.7 | 7.62,106.7 7.62,112.41 9.53,114.31 15.24,114.31 IC13.3 | C1.1 5.71,143.52 6.35,144.16 6.99,144.16 IC1.16 | C2.1 33.66,143.52 34.29,144.16 34.92,144.16 IC2.16 | 44.45,102.25 44.45,106.7 7.62,106.7 | C23.1 92.08,13.99 92.71,14.62 93.34,14.62 IC23.14 | C25.1 81.92,80.03 82.55,80.66 83.19,80.66 IC25.16 | IC29.16 83.19,65.42 82.55,65.42 81.92,64.78 C29.1 80.64,64.78 78.11,62.24 70.48,62.24 69.85,61.61 64.77,61.61 v64.14,60.98 | C36.1 81.92,29.23 82.55,29.86 83.19,29.86 IC36.16 | C32.1 81.92,49.55 82.55,50.18 83.19,50.18 IC32.16 | v83.82,26.69 92.71,26.69 IC36.6 | C16.1 92.71,118.12 IC16.16 97.79,115.58 v118.75,115.58 | C3.1 61.59,143.52 62.23,144.16 62.87,144.16 IC3.16 | 72.39,116.86 71.75,117.49 68.58,117.49 | 72.39,116.86 v73.03,116.22 | 68.58,117.49 66.04,117.49 C15.1 | 68.58,117.49 IC15.14 | v87.63,116.86 72.39,116.86 | v46.35,13.99 C41.1 64.77,13.99 IC41.16 | v63.5,39.38 62.23,40.66 IC35.20 | SV1.25 SV1.26 IC34.20 | 47.62,72.41 46.35,71.14 RS08.2 | 47.62,72.41 57.15,72.41 58.42,73.67 IC28.20 | 47.62,72.41 27.94,72.41 26.67,73.67 IC26.20 v20.32,73.67 | v20.32,44.47 22.23,44.47 23.5,43.2 C34.1 | C43.1 173.35,16.53 173.99,17.16 174.62,17.16 INTENB.16 | C46.1 128.27,27.32 129.54,26.05 DMA0-3.16 130.81,25.41 132.72,27.32 140.97,27.32 141.6,26.69
  Bottom 0.508: 141.6,26.69 142.88,25.41 C40.1 | 141.6,26.69 154.94,26.69 158.75,30.5 IC38.20 | v166.37,30.5 163.83,33.04 C38.1 | C39.1 128.91,62.24 129.54,61.61 137.16,61.61 137.79,60.98 141.6,60.98 142.88,62.24 C42.1 143.51,61.61 144.15,61.61 144.15,60.98 | v126.36,59.7 DMA4-7.16 | 144.15,60.98 144.15,60.34 DAR4-7.16 | 144.15,60.98 v154.94,60.98 161.29,60.98 162.56,62.24 176.53,62.24 v177.8,60.98 186.06,60.98 187.32,59.7 191.13,59.7 193.68,62.24 202.56,62.24 203.84,63.52 C30.1 | C6.1 145.41,143.52 146.05,144.16 146.69,144.16 IC6.16 | C18.1 147.96,118.12 148.59,118.76 149.22,118.76 IC18.14 | C17.1 120.02,118.12 120.65,118.76 121.28,118.76 IC17.16 | IC9.14 118.75,131.46 118.11,131.46 117.47,130.82 C9.1 116.84,130.19 143.51,130.19 144.15,130.82 C10.1 145.41,130.82 146.05,131.46 146.69,131.46 IC10.14 149.22,130.19 158.12,130.19 158.75,130.82 158.75,134.63 189.87,134.63 194.31,139.08 C45.+ 196.22,138.44 205.74,138.44 IC8.8 | C4.1 89.53,143.52 90.17,144.16 90.81,144.16 IC4.16 | IC5.14 118.75,144.16 118.11,144.16 117.47,143.52 C5.1 114.3,143.52 112.39,141.62 92.08,141.62 v91.44,140.98 | C8.1 128.91,96.53 129.54,95.9 137.16,95.9 137.79,95.27 141.6,95.27 142.88,96.53 C27.1 144.15,96.53 144.78,97.17 150.5,97.17 151.13,97.81 155.57,97.81 156.84,99.08 IC24.20 C19.1 | C12.1 203.84,114.31 198.75,119.39 RA.1 | C7.1 170.81,130.82 171.45,131.46 172.09,131.46 IC7.16 | C11.1 173.35,118.12 173.99,118.76 174.62,118.76 IC11.14 177.16,121.3 183.51,121.3 IC11.10 187.32,117.49 193.04,117.49 194.94,119.39 RL.1
WE\  (via drill 0.61)
  Top 0.254: v47.62,75.58 46.99,74.95 46.99,65.42 45.72,64.15 RS08.8 | v78.74,80.66 IC22.5 v81.92,99.71 | v135.89,139.08 135.89,109.23 126.36,99.71 123.83,99.71 v123.83,98.44
  Bottom 0.254: v78.74,80.66 52.7,80.66 v47.62,75.58 | v135.89,139.08 136.53,139.71 154.94,139.71 IC6.5 | v123.83,98.44 123.19,99.08 90.81,99.08 90.17,98.44 83.19,98.44 v81.92,99.71
WLS  (via drill 0.61)
  Top 0.254: v203.2,22.88 202.56,22.24 202.56,3.19 203.84,1.92 206.38,1.92 206.38,4.46 210.82,8.91 210.82,130.19 190.5,150.51 130.81,150.51 130.81,140.98 v130.18,140.35 | v132.08,139.71 133.35,138.44 133.35,129.55 129.54,125.75 IC9.5 | v39.37,29.23 38.73,29.86 38.73,45.1 40.64,47.01 40.64,48.27 39.37,49.55 38.1,49.55 38.1,47.01 37.47,46.37 37.47,15.89 v40.64,12.71 | v71.12,12.71 72.39,13.99 72.39,19.7 75.56,22.88 v75.56,31.77 | v138.43,34.3 147.32,25.41 v147.32,20.34
  Bottom 0.254: v130.18,140.35 130.81,139.71 v132.08,139.71 | v203.2,22.88 IC37.4 196.85,22.88 195.58,24.14 182.25,24.14 179.71,21.61 151.13,21.61 150.5,20.97 147.96,20.97 v147.32,20.34 | v39.37,29.23 37.47,29.23 36.2,27.96 SV1.15 | v40.64,12.71 41.91,11.45 69.85,11.45 v71.12,12.71 | v75.56,31.77 78.11,34.3 v138.43,34.3
WLS\  (via drill 0.61)
  Top 0.254: v133.35,107.97 133.35,121.94 132.08,123.2 IC9.6 | v148.59,107.33 151.76,107.33 v151.76,108.6
  Bottom 0.254: v133.35,107.97 134.62,106.7 147.96,106.7 v148.59,107.33 | v151.76,108.6 152.4,109.23 195.58,109.23 196.85,110.5 203.2,110.5 204.47,109.23 IC12.13
WRITING  (via drill 0.61)
  Top 0.254: IC6.2 151.76,135.27 158.75,135.27 158.75,127.02 157.48,125.75 IC10.5 | RS08.18 45.09,50.81 45.09,49.55 42.55,49.55 41.91,48.91 41.91,21.61 v40.64,20.34 43.18,17.8 43.18,5.09 61.59,5.09 64.77,8.27 64.77,8.91 67.31,11.45 67.31,20.34 67.94,20.34 | 67.94,20.34 68.58,20.34 69.85,19.07 69.85,17.8 71.12,16.53 IC41.14 | v174.62,116.22 176.53,114.31 176.53,45.73 173.99,43.2 v173.99,34.3 | v118.11,33.04 116.2,31.13 v116.2,30.5 | v69.85,31.77 67.94,29.86 67.94,20.34
  Bottom 0.254: IC41.14 71.75,14.62 73.03,14.62 IC41.13 | v40.64,20.34 SV1.9 | v174.62,116.22 172.72,116.22 167.64,121.3 160.66,121.3 IC10.5 | v173.99,34.3 145.41,34.3 144.15,33.04 v118.11,33.04 | v116.2,30.5 114.94,29.23 102.87,29.23 101.6,27.96 78.11,27.96 74.3,31.77 v69.85,31.77

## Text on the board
Bottom: RS08 | VRS | RF08 Debug | VRS | RS08 | VRS | RF08 | VRS
tPlace: RF08 | VRS
tValues: RF08 Debug | VRS | RS08 | VRS | RS08 | VRS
